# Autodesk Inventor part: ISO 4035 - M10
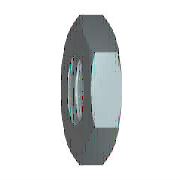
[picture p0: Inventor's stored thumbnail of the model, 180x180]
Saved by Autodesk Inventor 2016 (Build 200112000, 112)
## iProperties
Created: 2013-10
Part Number: ISO 4035 - M10
Material: Stainless Steel, 440C
Description: HEX NUT SST
Document SubType Name: Modeling
Standard: ISO 4035
Designer: normanpa
Standard Revision: Third edition 1999-08-15
Standards Organization: ISO
Language: en-US
Size Designation: M10
Categories: <MemberInstance><Categories><Category DisplayName="Fasteners" InternalName="e4da775c-781d-43d5-af7c-5136215cf5a6" Mnemonic="FSTN"><Category DisplayName="Nuts" I
Density: 7.75 g/cm^3
Appearance: Semi-Polished
IsCustomPart: 0
Author: normanpa
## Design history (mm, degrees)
sketch "Sketch1"
  geometry: L1 (-9.238, 0)-(-4.619, 8); L2 (-4.619, 8)-(4.619, 8); L3 (4.619, 8)-(9.238, 0); L4 (9.238, 0)-(4.619, -8); L5 (4.619, -8)-(-4.619, -8); L6 (-4.619, -8)-(-9.238, 0); 2 further points
  constraints: 12 end point, 1 coincident, 1 horizontal, 11 other
  dimensions: "d0" = 18.47521 distance of L3.end L1.start (= 1.1547 x SW)
extrude "Body" new body sketch "Sketch1" distance "d1" = 5 (= KOH); taper "d2" = 0 deg
sketch "Sketch2"
  geometry: L1 (0, 4.619)-(0, 9.238) reference; L2 (0, 9.238)-(5, 9.238) reference; L3 (5, 4.619)-(5, 9.238) reference; L4 (-1, 0)-(6, 0) reference; L5 (1.119, 9.238)-(0, 7.3); L6 (3.881, 9.238)-(5, 7.3)
  constraints: 4 end point, 4 point on line
  dimensions: "d3" = 30 deg angle of L1 L5 (= ANG1); "d4" = 30 deg angle of L3 L6 (= ANG2); "d5" = 14.6 diameter of L5.end L4 (= SW0); "d6" = 14.6 diameter of L6.end L4 (= SW01)
revolve "Chamfer1" sketch "Sketch2" stored, may be unused: angle "d7" = 90 deg
sketch "Sketch3"
  geometry: 4 further points
  constraints: 1 coincident, 1 other
hole "Thread" sketch "Sketch3" at (0, 0) diameter "d25" = 8.376; stored, may be unused: countersink angle "d29" = 82 deg, drill point angle "d31" = 118 deg; dims "d26" = 6, "d27" = 4, "d28" = 2, "d30" = 8
workaxis "Work Axis1"
workplane "Work Plane1"
body "Solid1"
chamfer "Chamfer2" distance "d8" = 0.8119 (= -0.5 x GD1 + 0.5 x NND); stored, may be unused: angle "d9" = 30 deg, second distance "d40" = 0.8119 (= -0.5 x GD1 + 0.5 x NND)
chamfer "Chamfer3" distance "d10" = 0.8119 (= -0.5 x GD1 + 0.5 x NND); stored, may be unused: angle "d11" = 30 deg, second distance "d41" = 0.8119 (= -0.5 x GD1 + 0.5 x NND)
other parameters: "ANG1" = 30 deg [user parameter; used in 1 equation term], "ANG2" = 30 deg [user parameter; used in 1 equation term], "KOH" = 5 [user parameter; used in 1 equation term], "SW" = 16 [user parameter; used in 2 equation terms], "SW0" = 14.6 [user parameter; used in 2 equation terms], "SW01" = 14.6 (= SW0) [user parameter; used in 1 equation term], "GD1" = 8.3762 (computed from THREADDIA, PTC, TOA) [user parameter; used in 4 equation terms], "d13" = 0, "d14" = 0, "d39" = 0, "d42" = 0, "GUL" = 0.8119 (= 0.541266 x PTC) [user parameter], "TPU" = 6.66667 (computed from PTC) [user parameter], "TOA" = 30 deg [user parameter; used in 1 equation term], "PTC" = 1.5 [user parameter; used in 4 equation terms], "E0" = 18.48 (= 1.155 x SW) [user parameter], "GAL" = 0.8119 (= 0.541266 x PTC) [user parameter]
